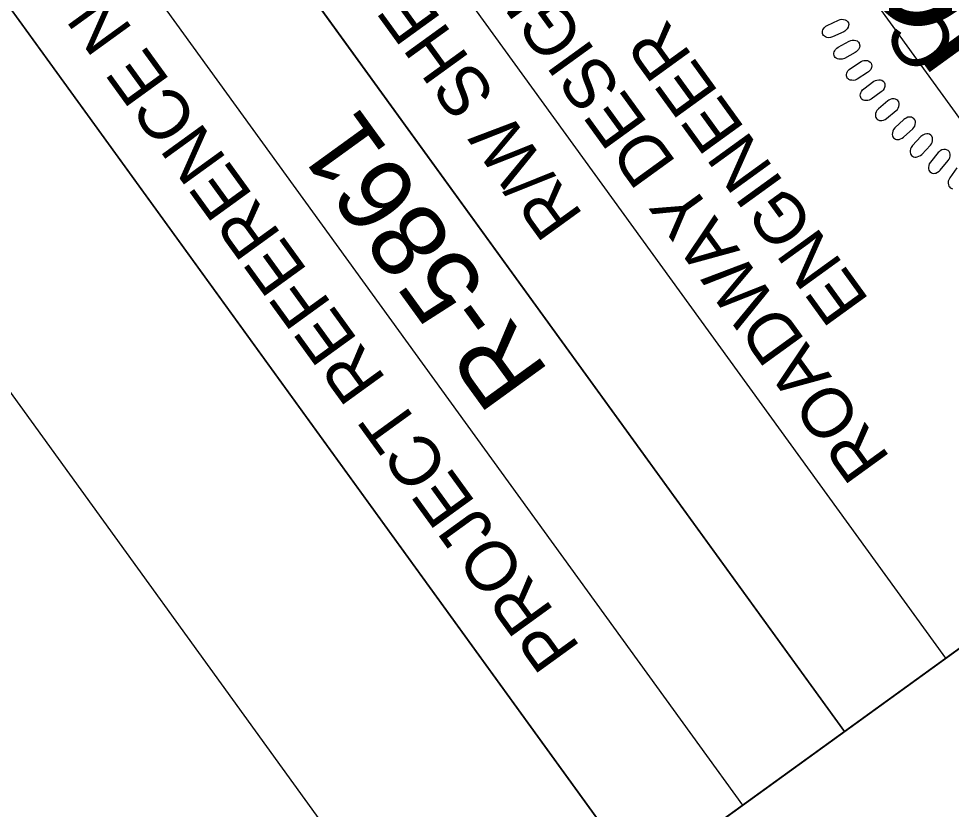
# Model space of a CAD drawing. Extents: x 474248 to 476123, y 501895 to 503900.
# Drawn here: x 474331.8 to 474424.9, y 503102.6 to 503181.5 of the extents above; entities that cross this region are included whole.
import ezdxf

# ---------------------------------------------------------------- set-up
doc = ezdxf.new("R2010")
doc.units = 0
for name, color, linetype in [('Prop Grid Mask', 7, 'Continuous'), ('Scratch_Level_5', 7, 'Continuous'), ('Sheet Data Field CELL', 7, 'Continuous'), ('Sheet Layout Plan Border', 7, 'Continuous'), ('Sheet PE Seal Cell', 7, 'Continuous'), ('Sheet Plan CELL', 7, 'Continuous'), ('Sheet Plot Border Outside CELL', 7, 'Continuous'), ('Sheet Sticker Incomplete CELL', 7, 'Continuous')]:
    doc.layers.add(name, color=color, linetype=linetype)

msp = doc.modelspace()

# ---------------------------------------------------------------- linework, layer by layer
at = {"layer": 'Prop Grid Mask'}
msp.add_lwpolyline([(474393.918, 503095.623), (474486.211, 502968.161), (474519.992, 502992.621), (474427.7, 503120.083)], close=True, dxfattribs=at)
at = {"layer": 'Scratch_Level_5'}
msp.add_lwpolyline([(474627.913, 502772.461), (474393.918, 503095.623), (474534.481, 503197.416), (474417.163, 503359.44), (475062.239, 503826.524), (475162.267, 503688.379), (475227.085, 503735.313), (475493.156, 503367.85)], close=True, dxfattribs=at)
at = {"layer": 'Sheet Layout Plan Border'}
msp.add_lwpolyline([(475148.793, 502314.888), (475799.674, 502786.065), (475874.954, 502840.561), (475397.529, 503499.918), (475353.895, 503468.323), (475265.228, 503590.778), (475283.66, 503604.124), (475199.913, 503719.785), (475161.571, 503692.033), (475161.571, 503692.033), (475161.571, 503692.033), (475161.571, 503692.033), (475161.571, 503692.033), (475063.524, 503827.461), (474417.163, 503359.44), (474534.481, 503197.416), (474393.908, 503095.616), (475024.421, 502224.855)], close=True, dxfattribs=at)
at = {"layer": 'Sheet PE Seal Cell'}
for points in [[(474414.162, 503180.219), (474413.051, 503179.7), (474412.836, 503179.641), (474412.688, 503179.629), (474412.487, 503179.659), (474412.346, 503179.7), (474412.227, 503179.768), (474412.146, 503179.845), (474412.08, 503179.939), (474412.051, 503180.048), (474412.027, 503180.17), (474412.037, 503180.29), (474412.083, 503180.427), (474412.13, 503180.514), (474412.237, 503180.639), (474412.374, 503180.77), (474412.509, 503180.858), (474413.644, 503181.397), (474413.807, 503181.448), (474413.952, 503181.467), (474414.135, 503181.453), (474414.309, 503181.411), (474414.423, 503181.357), (474414.543, 503181.24), (474414.625, 503181.113), (474414.652, 503180.961), (474414.651, 503180.845), (474414.615, 503180.688), (474414.512, 503180.507), (474414.378, 503180.37), (474414.273, 503180.288)], [(474415.302, 503178.157), (474414.225, 503177.568), (474414.015, 503177.495), (474413.868, 503177.475), (474413.665, 503177.491), (474413.522, 503177.524), (474413.398, 503177.584), (474413.313, 503177.656), (474413.242, 503177.745), (474413.206, 503177.854), (474413.174, 503177.972), (474413.177, 503178.093), (474413.214, 503178.233), (474413.255, 503178.324), (474413.354, 503178.455), (474413.483, 503178.593), (474413.612, 503178.689), (474414.711, 503179.299), (474414.871, 503179.361), (474415.014, 503179.388), (474415.197, 503179.386), (474415.374, 503179.355), (474415.49, 503179.308), (474415.618, 503179.199), (474415.708, 503179.078), (474415.744, 503178.927), (474415.751, 503178.812), (474415.724, 503178.652), (474415.633, 503178.465), (474415.507, 503178.321), (474415.408, 503178.232)], [(474416.545, 503176.141), (474415.508, 503175.485), (474415.303, 503175.399), (474415.157, 503175.369), (474414.953, 503175.374), (474414.809, 503175.397), (474414.681, 503175.449), (474414.592, 503175.517), (474414.515, 503175.601), (474414.473, 503175.706), (474414.434, 503175.823), (474414.428, 503175.944), (474414.456, 503176.085), (474414.492, 503176.178), (474414.582, 503176.316), (474414.702, 503176.462), (474414.825, 503176.566), (474415.884, 503177.243), (474416.039, 503177.315), (474416.181, 503177.352), (474416.364, 503177.361), (474416.541, 503177.341), (474416.661, 503177.301), (474416.796, 503177.201), (474416.893, 503177.085), (474416.939, 503176.937), (474416.952, 503176.822), (474416.936, 503176.661), (474416.856, 503176.47), (474416.741, 503176.317), (474416.646, 503176.222)], [(474417.907, 503174.214), (474416.914, 503173.495), (474416.714, 503173.397), (474416.569, 503173.357), (474416.367, 503173.349), (474416.221, 503173.363), (474416.09, 503173.407), (474415.997, 503173.468), (474415.915, 503173.548), (474415.866, 503173.65), (474415.819, 503173.765), (474415.807, 503173.884), (474415.826, 503174.028), (474415.856, 503174.123), (474415.938, 503174.265), (474416.048, 503174.419), (474416.164, 503174.531), (474417.178, 503175.273), (474417.328, 503175.355), (474417.468, 503175.4), (474417.649, 503175.421), (474417.829, 503175.412), (474417.95, 503175.38), (474418.091, 503175.287), (474418.194, 503175.178), (474418.249, 503175.034), (474418.27, 503174.92), (474418.265, 503174.758), (474418.197, 503174.562), (474418.091, 503174.402), (474418.003, 503174.302)], [(474418.569, 503173.316), (474417.622, 503172.536), (474417.476, 503172.367), (474417.402, 503172.239), (474417.342, 503172.044), (474417.319, 503171.899), (474417.329, 503171.762), (474417.364, 503171.656), (474417.421, 503171.556), (474417.508, 503171.483), (474417.606, 503171.41), (474417.719, 503171.366), (474417.863, 503171.349), (474417.962, 503171.354), (474418.121, 503171.397), (474418.297, 503171.465), (474418.434, 503171.549), (474419.409, 503172.343), (474419.526, 503172.468), (474419.605, 503172.591), (474419.671, 503172.762), (474419.707, 503172.937), (474419.708, 503173.063), (474419.654, 503173.222), (474419.574, 503173.35), (474419.448, 503173.44), (474419.343, 503173.489), (474419.185, 503173.524), (474418.978, 503173.508), (474418.797, 503173.446), (474418.678, 503173.387)], [(474420.163, 503171.46), (474419.267, 503170.622), (474419.132, 503170.445), (474419.066, 503170.311), (474419.018, 503170.113), (474419.005, 503169.967), (474419.023, 503169.831), (474419.066, 503169.727), (474419.127, 503169.631), (474419.219, 503169.564), (474419.322, 503169.497), (474419.437, 503169.461), (474419.582, 503169.453), (474419.681, 503169.464), (474419.836, 503169.517), (474420.008, 503169.596), (474420.14, 503169.688), (474421.062, 503170.541), (474421.171, 503170.673), (474421.243, 503170.801), (474421.298, 503170.976), (474421.323, 503171.153), (474421.315, 503171.279), (474421.252, 503171.434), (474421.164, 503171.557), (474421.033, 503171.639), (474420.925, 503171.681), (474420.765, 503171.706), (474420.56, 503171.678), (474420.383, 503171.604), (474420.268, 503171.537)], [(474421.857, 503169.747), (474421.016, 503168.855), (474420.892, 503168.669), (474420.834, 503168.532), (474420.8, 503168.331), (474420.795, 503168.185), (474420.822, 503168.05), (474420.871, 503167.949), (474420.939, 503167.857), (474421.034, 503167.795), (474421.141, 503167.735), (474421.259, 503167.707), (474421.404, 503167.707), (474421.502, 503167.725), (474421.653, 503167.787), (474421.82, 503167.877), (474421.946, 503167.977), (474422.813, 503168.887), (474422.913, 503169.025), (474422.976, 503169.158), (474423.02, 503169.335), (474423.035, 503169.514), (474423.019, 503169.639), (474422.945, 503169.79), (474422.85, 503169.907), (474422.714, 503169.98), (474422.604, 503170.016), (474422.443, 503170.031), (474422.24, 503169.989), (474422.068, 503169.905), (474421.957, 503169.831)], [(474423.592, 503168.156), (474422.808, 503167.213), (474422.696, 503167.02), (474422.647, 503166.879), (474422.625, 503166.677), (474422.63, 503166.531), (474422.665, 503166.398), (474422.72, 503166.3), (474422.794, 503166.213), (474422.892, 503166.156), (474423.004, 503166.104), (474423.122, 503166.083), (474423.267, 503166.093), (474423.363, 503166.115), (474423.511, 503166.188), (474423.671, 503166.288), (474423.791, 503166.396), (474424.599, 503167.358), (474424.691, 503167.502), (474424.745, 503167.639), (474424.778, 503167.819), (474424.781, 503167.998), (474424.757, 503168.121), (474424.675, 503168.268), (474424.573, 503168.378), (474424.432, 503168.444), (474424.32, 503168.472), (474424.158, 503168.476), (474423.958, 503168.422), (474423.791, 503168.327), (474423.686, 503168.247)]]:
    msp.add_lwpolyline(points, close=True, dxfattribs=at)
msp.add_lwpolyline([(474425.463, 503166.63), (474424.74, 503165.639), (474424.64, 503165.44), (474424.6, 503165.297), (474424.591, 503165.094), (474424.605, 503164.947), (474424.648, 503164.817), (474424.709, 503164.723), (474424.788, 503164.641), (474424.891, 503164.59), (474425.005, 503164.545)], dxfattribs=at)
at = {"layer": 'Sheet Plan CELL'}
for p, q in [((474414.228, 503110.329), (474296.891, 503272.338)), ((474414.228, 503110.329), (474296.891, 503272.338)), ((474404.081, 503102.966), (474286.766, 503265.007)), ((474414.228, 503110.329), (474424.343, 503117.653))]:
    msp.add_line(p, q, dxfattribs=at)
for points in [[(474276.579, 503257.677), (475156.317, 502042.698), (476006.781, 502658.499), (475127.058, 503873.458)], [(476006.781, 502658.499), (475156.352, 502042.692), (474393.908, 503095.616), (474515.447, 503183.634), (474398.139, 503345.665), (475127.058, 503873.458)], [(474393.908, 503095.616), (474276.579, 503257.677), (474296.891, 503272.338), (474414.228, 503110.329)], [(474424.343, 503117.653), (474365.666, 503198.69), (474456.797, 503264.676), (474515.447, 503183.634)]]:
    msp.add_lwpolyline(points, close=True, dxfattribs=at)
at = {"layer": 'Sheet Plot Border Outside CELL'}
msp.add_lwpolyline([(475235.744, 501894.66), (474248.409, 503258.238), (475135.322, 503900.43), (476122.656, 502536.853)], close=True, dxfattribs=at)
at = {"layer": 'Sheet Sticker Incomplete CELL'}
msp.add_lwpolyline([(474454.332, 503172.147), (474435.298, 503158.364), (474349.086, 503277.429), (474368.12, 503291.211)], close=True, dxfattribs=at)

# ---------------------------------------------------------------- texts
at = {"layer": 'Sheet Data Field CELL'}
msp.add_text('R-5861', height=7.5, rotation=125.90742, dxfattribs=at).set_placement((474384.859, 503146.18))
at = {"layer": 'Sheet PE Seal Cell'}
msp.add_text('C', height=5.669, rotation=123.49152, dxfattribs=at).set_placement((474425.803, 503178.665))
at = {"layer": 'Sheet Plan CELL'}
for s, p in [('R/W SHEET NO.', (474388.241, 503161.885)), ('PROJECT REFERENCE NO.', (474387.956, 503118.714)), ('ROADWAY DESIGN', (474418.893, 503137.627)), ('ENGINEER', (474416.794, 503153.377))]:
    msp.add_text(s, height=5.0001, rotation=125.90742, dxfattribs=at).set_placement(p)
at = {"layer": 'Sheet Sticker Incomplete CELL'}
for s, height, p in [('INCOMPLETE PLANS', 11.52, (474439.607, 503172.534)), ('DO NOT USE FOR R/W ACQUISITION', 5.76, (474443.33, 503179.242))]:
    msp.add_text(s, height=height, rotation=125.90742, dxfattribs=at).set_placement(p)

doc.saveas('drawing.dxf')
